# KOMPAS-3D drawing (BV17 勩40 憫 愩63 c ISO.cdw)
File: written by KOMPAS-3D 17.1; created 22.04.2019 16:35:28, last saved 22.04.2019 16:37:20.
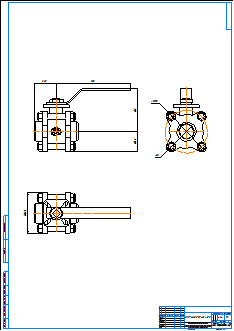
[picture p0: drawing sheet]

Sheet 1: A1, portrait

Title block, sheet 1: name: BV17 Ду40 СС Ру63 c ISO; material: Внимание! Данный продукт является объектом авторского права ООО «Торговый Дом АДЛ». / Запрещается изменение, копирование, распространение / (в том числе путем копирования на другие сайты и ресурсы в Интернете) / или любое иное использование информации и объектов без предварительного / согласия правообладателя (ООО «Торговый Дом АДЛ»).; mass: 4,44; sheets: 1; organisation: ООО "Торговый дом АДЛ"; sheet format: A1

Views: Спереди 1, Проекционный вид 2, Проекционный вид 3
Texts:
  user
Dimensions and other numbers on the sheet: 56,5; 188; 109; 51,62; 103,24; 38; 109,8; 1:1; 1; 4,44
